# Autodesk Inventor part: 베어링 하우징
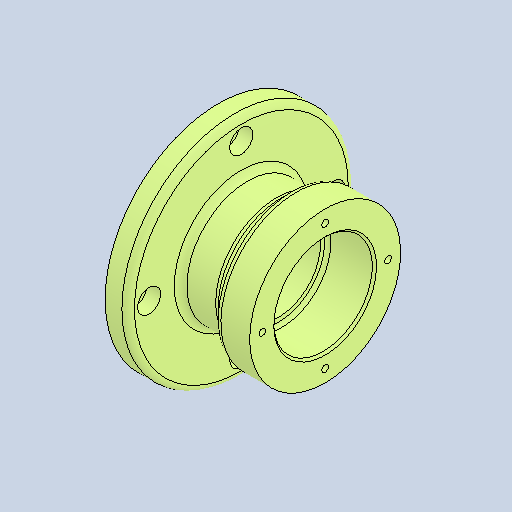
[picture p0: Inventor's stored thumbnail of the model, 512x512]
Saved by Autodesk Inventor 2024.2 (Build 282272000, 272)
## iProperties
Created: 2026-01
Part Number: 베어링 하우징
Material: 알루미늄 6061
Document SubType Name: Modeling
Designer: home
Density: 2.7 g/cm^3
Appearance: 기본값
Author: jhkim
Sending System: Autodesk Inventor 2026
Preprocessor: ST-DEVELOPER v20.1
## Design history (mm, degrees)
feature "솔리드1"
node "솔리드2"
